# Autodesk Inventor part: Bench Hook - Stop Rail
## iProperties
Created: 2010-02
Part Number: Bench Hook - Stop Rail
Document SubType Name: Modeling
Designer: Munford
Density: 1 g/cm^3
Length: 150.000 mm
Width: 44.000 mm
Thickness: 19.000 mm
Author: Munford
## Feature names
1. Extrusion1
